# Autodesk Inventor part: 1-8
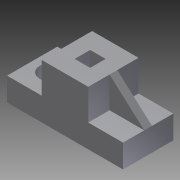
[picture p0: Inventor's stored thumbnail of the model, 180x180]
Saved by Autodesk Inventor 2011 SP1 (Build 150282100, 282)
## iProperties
Created: 2014-02
Part Number: 1-8
Document SubType Name: Modeling
Designer: Administrator
Density: 1 g/cm^3
Author: Administrator
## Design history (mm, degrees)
sketch "草图1"
  geometry: L1 (-15, 6.5)-(15, 6.5); L2 (15, 6.5)-(15, -6.5); L3 (15, -6.5)-(-15, -6.5); L4 (-15, -6.5)-(-15, 6.5); 3 further points
  constraints: 8 end point, 2 midpoint, 2 parallel, 1 horizontal, 1 horizontal alignment, 1 perpendicular, 1 vertical alignment
extrude "拉伸1" new body sketch "草图1" distance "d0" = 6; taper "d1" = 0 deg
sketch "草图2"
  geometry: L1 (-15, 6.5)-(15, 6.5) reference; L2 (15, -6.5)-(-15, -6.5) reference; L3 (-6, 6.5)-(6, 6.5); L4 (6, 6.5)-(6, -6.5); L5 (6, -6.5)-(-6, -6.5); L6 (-6, -6.5)-(-6, 6.5); 2 further points
  constraints: 8 end point, 2 parallel, 2 point on line, 1 horizontal, 1 midpoint, 1 perpendicular, 1 vertical alignment
  dimensions: "d2" = 12 distance of L4.end L5.end
extrude "拉伸2" join sketch "草图2" distance "d3" = 8; taper "d4" = 0 deg
sketch "草图3"
  geometry: L1 (-2, -2)-(2, -2); L2 (2, -2)-(2, 2); L3 (2, 2)-(-2, 2); L4 (-2, 2)-(-2, -2); 1 further point
  constraints: 8 end point, 2 parallel, 1 horizontal, 1 perpendicular
extrude "拉伸3" cut sketch "草图3" stored distance "d5" = 8; taper "d6" = 0 deg
sketch "草图4"
  geometry: L1 (-2, -2)-(-2, 2) reference; L2 (-2, 2)-(2, 2) reference; L3 (2, 2)-(2, -2) reference; L4 (2, -2)-(-2, -2) reference; L5 (-4, -4)-(4, -4); L6 (4, -4)-(4, 4); L7 (4, 4)-(-4, 4); L8 (-4, 4)-(-4, -4); 1 further point
  constraints: 8 end point, 2 parallel, 1 horizontal, 1 perpendicular
extrude "拉伸4" cut sketch "草图4" distance "d7" = 2; taper "d8" = 0 deg
sketch "草图5"
  geometry: C1 r 3 at (-10, 0); 1 further point
  constraints: 1 centre point
  dimensions: "d9" = 6 diameter of C1
extrude "拉伸5" cut sketch "草图5" stored distance "d10" = 2; taper "d11" = 0 deg
sketch "草图6"
  geometry: L1 (-6, 6)-(-6, 14) reference; L2 (-6, 6)-(-15, 6) reference; L3 (-6, 14)-(-15, 6); 1 further point
  constraints: 2 end point
extrude "拉伸6" join sketch "草图6" stored distance "d12" = 2; taper "d13" = 0 deg
node "实体1"
